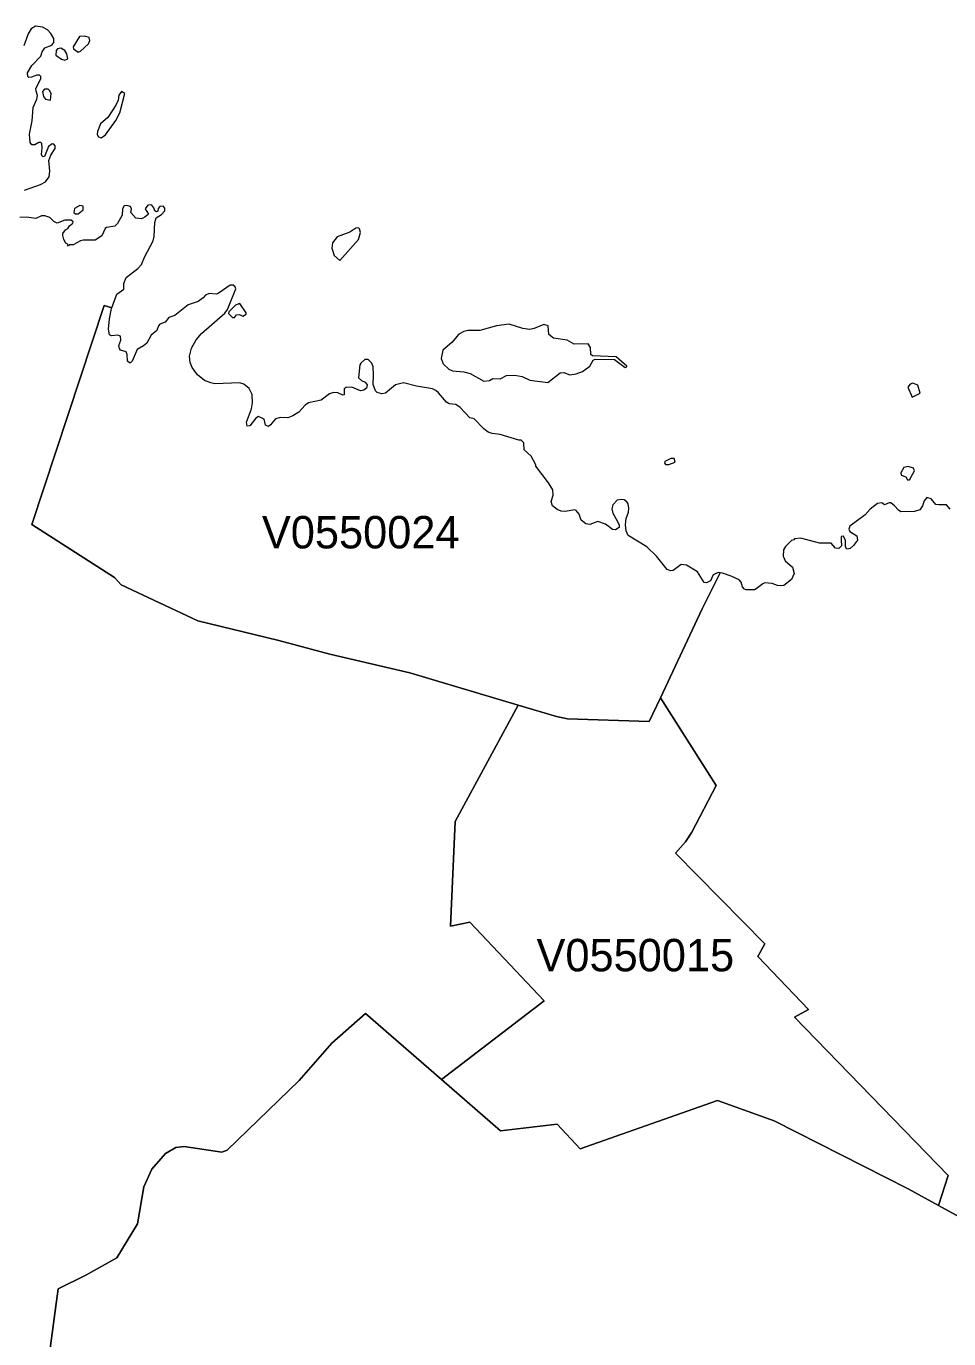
# Model space of a CAD drawing. Extents: x 369010 to 735936, y 6377141 to 6616555.
# Drawn here: x 445399 to 448245, y 6488735 to 6492786 of the extents above; entities that cross this region are included whole.
import ezdxf
from ezdxf.enums import TextEntityAlignment as Align

# ---------------------------------------------------------------- set-up
doc = ezdxf.new("R2010")
doc.units = 0
doc.header["$LTSCALE"] = 40
doc.layers.add('3', color=7, linetype='Continuous', lineweight=13)
doc.layers.add('4', color=7, linetype='Continuous')

msp = doc.modelspace()

# ---------------------------------------------------------------- linework, layer by layer
at = {"layer": '3'}
for points in [[(445393.45, 6492279.97), (445442.77, 6492297.35), (445458.32, 6492305.95), (445469.25, 6492320.68), (445471.56, 6492338.56), (445467.92, 6492371.82), (445474.71, 6492388.54), (445488.11, 6492409.06), (445488.45, 6492416.67), (445484.31, 6492421.8), (445479.18, 6492422.8), (445467.59, 6492414.69), (445455.51, 6492384.4), (445450.71, 6492382.75), (445447.57, 6492384.73), (445446.24, 6492390.03), (445447.9, 6492410.88), (445446.57, 6492423.96), (445443.43, 6492427.27), (445437.97, 6492427.27), (445425.39, 6492419.82), (445416.12, 6492420.15), (445411.32, 6492427.27), (445409.17, 6492452.42), (445417.44, 6492494.13), (445419.76, 6492535.67), (445431.84, 6492560.66), (445433.17, 6492571.92), (445429.03, 6492585.65), (445428.7, 6492593.93), (445443.43, 6492623.72), (445443.43, 6492631), (445440.12, 6492634.81), (445431.18, 6492635.14), (445415.13, 6492629.18), (445406.19, 6492628.19), (445403.38, 6492631), (445402.38, 6492642.59), (445416.12, 6492664.27), (445443.76, 6492693.4), (445447.57, 6492707.13), (445456.17, 6492719.38), (445477.19, 6492727.32), (445483.65, 6492735.27), (445483.65, 6492748.18), (445474.71, 6492763.24), (445464.45, 6492775.32), (445448.56, 6492782.93), (445427.71, 6492785.91), (445413.64, 6492778.13), (445405.03, 6492762.25), (445391.13, 6492725.67)], [(445441.77, 6488475.03), (445489.27, 6488828.22), (445497.55, 6488889.29), (445582.12, 6488931.66), (445678.44, 6488985.11), (445742.16, 6489090.21), (445761.03, 6489203.74), (445786.52, 6489258.69), (445828.72, 6489306.69), (445860.5, 6489326.05), (445885.65, 6489328.53), (446002.67, 6489311.65), (446018.55, 6489317.28), (446240.99, 6489531.94), (446341.29, 6489647.13), (446445.72, 6489739.15), (446679.91, 6489535.25), (446996.35, 6489778.21), (446767.29, 6490021), (446707.71, 6490008.76), (446721.95, 6490331.16), (446916.74, 6490690.96), (446582.59, 6490790.6), (446335.49, 6490848.19), (446177.93, 6490889.73), (445928.02, 6490951.14), (445691.52, 6491062.02), (445671, 6491084.37), (445416.12, 6491248.55), (445639.05, 6491924.13), (445662.39, 6491917.18), (445678.44, 6491959.22), (445699.96, 6491974.45), (445699.96, 6491992.49), (445706.74, 6492010.36), (445742.82, 6492038.17), (445754.08, 6492050.25), (445763.68, 6492073.09), (445789.83, 6492123.9), (445793.3, 6492136.64), (445795.62, 6492179.84), (445800.09, 6492194.57), (445816.47, 6492204.83), (445826.57, 6492216.08), (445826.57, 6492224.69), (445821.27, 6492231.14), (445811.34, 6492229.82), (445806.21, 6492223.03), (445804.23, 6492215.09), (445800.42, 6492213.43), (445795.95, 6492216.08), (445792.48, 6492225.35), (445786.35, 6492233.63), (445782.55, 6492235.28), (445774.11, 6492233.63), (445765.83, 6492222.54), (445775.43, 6492206.15), (445764.84, 6492196.55), (445754.41, 6492191.42), (445737.03, 6492193.74), (445721.14, 6492210.62), (445723.3, 6492222.7), (445720.48, 6492229.49), (445709.56, 6492232.96), (445700.62, 6492232.14), (445696.15, 6492222.21), (445694.5, 6492203.01), (445680.76, 6492177.35), (445671.82, 6492168.75), (445646.17, 6492164.61)], [(445646.17, 6492164.61), (445642.36, 6492161.63), (445631.44, 6492138.63), (445611.25, 6492125.22), (445573.85, 6492125.88), (445566.56, 6492123.9), (445543.89, 6492111.15), (445531.64, 6492111.15), (445529.16, 6492107.35), (445526.18, 6492111.82), (445528.17, 6492112.48), (445520.39, 6492116.28), (445514.76, 6492127.37), (445511.45, 6492140.28), (445512.11, 6492146.57), (445519.89, 6492157.83), (445527.17, 6492161.63), (445531.97, 6492170.07), (445542.9, 6492178.68), (445543.89, 6492182.15), (445537.43, 6492186.95), (445518.24, 6492186.95), (445494.24, 6492178.35), (445483.65, 6492183.15), (445471.56, 6492195.56), (445456.17, 6492200.69), (445446.24, 6492200.36), (445428.04, 6492193.08), (445399.9, 6492196.88), (445378.72, 6492195.23)], [(446424.37, 6491700.87), (446433.31, 6491692.59), (446444.73, 6491687.13), (446450.85, 6491679.19), (446448.86, 6491668.6), (446440.59, 6491662.31), (446430, 6491660.98), (446403.19, 6491671.57), (446385.97, 6491671.24), (446379.19, 6491666.78), (446379.19, 6491647.91), (446376.04, 6491646.91), (446360.32, 6491654.2), (446346.25, 6491655.52), (446334.67, 6491651.38), (446308.19, 6491631.52), (446270.12, 6491623.58), (446259.53, 6491616.46), (446239.34, 6491594.45), (446221.46, 6491583.2), (446205.74, 6491577.07), (446183.07, 6491578.06), (446168, 6491574.26), (446152.61, 6491555.39), (446145.99, 6491550.26), (446136.72, 6491554.4), (446132.59, 6491573.27), (446115.21, 6491581.04), (446106.93, 6491575.91), (446088.4, 6491552.58), (446080.62, 6491551.25), (446078.14, 6491564.33), (446093.53, 6491604.71), (446097.33, 6491623.91), (446095.35, 6491649.4), (446086.74, 6491668.26), (446070.52, 6491681.17), (446057.61, 6491685.64), (445980.82, 6491682), (445968.08, 6491684.98), (445948.88, 6491692.92), (445926.87, 6491709.64), (445910.48, 6491732.65), (445904.69, 6491748.04), (445902.54, 6491767.24), (445908.16, 6491792.72), (445922.89, 6491818.05), (445939.28, 6491837.24), (446011.6, 6491900.63), (446019.88, 6491912.05), (446045.2, 6491975.11), (446043.21, 6491981.89), (446037.09, 6491986.36), (446027.49, 6491986.36), (445991.08, 6491961.04), (445984.63, 6491958.89), (445962.95, 6491961.37), (445951.69, 6491955.91), (445944.41, 6491947.3), (445929.35, 6491936.05), (445898.56, 6491926.45), (445857.35, 6491892.85), (445838.82, 6491887.56), (445827.23, 6491872.5), (445810.68, 6491866.7), (445806.54, 6491860.91), (445802.08, 6491847.17), (445783.7, 6491832.78), (445770.96, 6491808.12), (445760.7, 6491799.18), (445741.17, 6491788.25), (445725.28, 6491751.84), (445720.48, 6491747.04), (445717.5, 6491746.71), (445711.54, 6491752.51), (445710.22, 6491772.37), (445707.24, 6491780.97), (445690.03, 6491786.1), (445686.22, 6491790.9), (445683.91, 6491800.83), (445690.36, 6491817.05), (445689.7, 6491828.97), (445681.42, 6491832.11), (445661.56, 6491830.13), (445655.77, 6491833.44), (445652.96, 6491850.98), (445655.77, 6491882.92), (445661.56, 6491915.03), (445662.39, 6491917.18)], [(445662.39, 6491917.18), (445639.05, 6491924.13), (445416.12, 6491248.55), (445671, 6491084.37), (445691.52, 6491062.02), (445928.02, 6490951.14), (446177.93, 6490889.73), (446335.49, 6490848.19), (446582.59, 6490790.6), (446916.74, 6490690.96), (447034.75, 6490655.71), (447068.68, 6490648.76), (447321.07, 6490640.65), (447355.5, 6490713.64), (447484.42, 6490987.55), (447540.03, 6491098.77), (447533.25, 6491099.76), (447518.19, 6491093.3), (447509.91, 6491074.11), (447497.33, 6491068.48), (447490.71, 6491069.47), (447469.86, 6491102.08), (447435.6, 6491122.76), (447419.38, 6491125.08), (447394.39, 6491106.21), (447387.93, 6491105.22), (447376.18, 6491109.36), (447342.92, 6491150.57), (447313.79, 6491178.87), (447256.19, 6491214.29), (447250.07, 6491228.35), (447247.26, 6491247.55), (447250.07, 6491266.75), (447257.35, 6491285.95), (447258.34, 6491298.86), (447255.53, 6491311.6), (447252.06, 6491318.06), (447243.28, 6491324.02), (447235.67, 6491325.67), (447222.26, 6491322.86), (447208.86, 6491308.96), (447205.55, 6491296.21), (447208.2, 6491283.47), (447222.26, 6491259.8), (447227.73, 6491246.39), (447227.73, 6491238.62), (447216.8, 6491232), (447207.54, 6491232.82), (447185.69, 6491249.21), (447162.68, 6491257.15), (447137.2, 6491248.55), (447125.28, 6491249.87), (447111.21, 6491261.29), (447104.26, 6491279.66), (447095.82, 6491291.41), (447090.36, 6491293.73), (447062.22, 6491288.27), (447049.48, 6491289.59), (447037.07, 6491294.06), (447022.83, 6491306.14), (447018.36, 6491319.22), (447024.49, 6491338.42), (447023.83, 6491355.13), (447010.42, 6491376.81), (446970.7, 6491428.12), (446970.7, 6491431.92), (446956.96, 6491459.4), (446935.28, 6491478.27), (446934.29, 6491500.28), (446925.35, 6491508.39), (446918.9, 6491508.39), (446861.3, 6491526.26), (446835.81, 6491528.74), (446823.57, 6491533.54), (446810.49, 6491543.47), (446781.2, 6491574.26), (446766.96, 6491576.91), (446737.83, 6491609.18), (446724.1, 6491618.12), (446703.24, 6491620.93), (446695.3, 6491625.4), (446670.97, 6491654.86), (446662.7, 6491661.64), (446651.77, 6491666.44), (446602.78, 6491675.38), (446562.57, 6491685.31), (446537.57, 6491679.19), (446506.79, 6491653.04), (446495.37, 6491651.71), (446481.97, 6491655.52), (446476.83, 6491660.32), (446468.73, 6491680.51), (446470.38, 6491709.64), (446469.06, 6491735.13), (446464.59, 6491745.72), (446453.66, 6491756.97), (446443.57, 6491757.31), (446430.66, 6491746.05), (446428.18, 6491741.25), (446424.37, 6491700.87)], [(448249.22, 6491295.22), (448238.46, 6491309.29), (448214.13, 6491308.46), (448205.03, 6491310.28), (448190.63, 6491327.82), (448177.22, 6491331.79), (448169.28, 6491320.87), (448164.48, 6491305.81), (448156.2, 6491293.73), (448139.82, 6491287.94), (448097.62, 6491287.61), (448089.67, 6491292.41), (448078.09, 6491306.14), (448066.5, 6491315.08), (448061.37, 6491315.08), (448046.97, 6491309.29), (448039.03, 6491314.75), (448025.29, 6491312.6), (448002.29, 6491295.22), (447987.56, 6491278.34), (447939.56, 6491242.75), (447937.24, 6491234.15), (447939.56, 6491226.2), (447961.9, 6491212.96), (447963.89, 6491199.56), (447951.14, 6491183.01), (447940.88, 6491174.07), (447930.29, 6491172.08), (447926.15, 6491179.2), (447926.48, 6491198.4), (447920.36, 6491212.47), (447913.58, 6491211.14), (447912.75, 6491199.56), (447914.57, 6491182.34), (447906.29, 6491174.07), (447896.03, 6491174.73), (447882.29, 6491190.29), (447846.05, 6491190.62), (447788.62, 6491205.68), (447769.42, 6491203.69), (447766.77, 6491200.88), (447759.99, 6491199.23), (447741.78, 6491180.69), (447735.49, 6491169.6), (447733.84, 6491150.9), (447740.79, 6491136.17), (447763.3, 6491116.47), (447768.1, 6491096.94), (447759.49, 6491078.08), (447735.99, 6491060.37), (447729.7, 6491058.88), (447716.79, 6491060.04), (447699.91, 6491066.16), (447677.9, 6491067.82), (447671.11, 6491065.17), (447651.25, 6491049.28), (447645.79, 6491046.96), (447620.3, 6491046.3), (447614.84, 6491048.95), (447608.72, 6491055.57), (447604.25, 6491070.3), (447598.79, 6491077.08), (447573.8, 6491088.5), (447547.31, 6491097.61), (447540.03, 6491098.77)], [(447540.03, 6491098.77), (447484.42, 6490987.55), (447355.5, 6490713.64), (447527.95, 6490442.87), (447452.48, 6490298.39), (447433.12, 6490268.93), (447401.67, 6490233.68), (447677.9, 6489954.14), (447656.05, 6489915.08), (447812.29, 6489751.89), (447769.26, 6489728.23), (448243.59, 6489239.49), (448213.96, 6489146.65), (448485.89, 6488997.86)], [(446862.13, 6489376.7), (446679.91, 6489535.25), (446445.72, 6489739.15), (446341.29, 6489647.13), (446240.99, 6489531.94), (446018.55, 6489317.28), (446002.67, 6489311.65), (445885.65, 6489328.53), (445860.5, 6489326.05), (445828.72, 6489306.69), (445786.52, 6489258.69), (445761.03, 6489203.74), (445742.16, 6489090.21), (445678.44, 6488985.11), (445582.12, 6488931.66), (445497.55, 6488889.29), (445489.27, 6488828.22), (445441.77, 6488475.03), (445433.17, 6488413.3)], [(449204.67, 6488728.75), (449205, 6488771.78), (449202.69, 6488788.5), (449191.76, 6488804.55), (449193.09, 6488819.28), (449185.31, 6488830.2), (449164.79, 6488845.92), (449154.86, 6488866.78), (449152.04, 6488883.49), (449144.43, 6488898.22), (449128.71, 6488892.76), (448742.75, 6488821.76), (448485.89, 6488997.86), (448213.96, 6489146.65), (448119.96, 6489198.12), (447706.53, 6489407.81), (447531.1, 6489470.87), (447108.07, 6489321.75), (447036.9, 6489397.55), (446862.13, 6489376.7)]]:
    msp.add_lwpolyline(points, dxfattribs=at)
for points in [[(445578.98, 6492755.13), (445562.76, 6492754.14), (445543.23, 6492722.86), (445544.72, 6492715.74), (445558.78, 6492706.14), (445566.23, 6492709.12), (445590.89, 6492731.79), (445594.7, 6492741.72), (445592.38, 6492751.65)], [(445505.49, 6492718.06), (445494.9, 6492716.07), (445490.76, 6492710.94), (445489.77, 6492696.54), (445507.97, 6492684.13), (445517.9, 6492681.31), (445527.17, 6492685.45), (445524.36, 6492700.51), (445517.9, 6492710.94)], [(445470.9, 6492587.8), (445466.43, 6492591.94), (445454.85, 6492591.94), (445449.06, 6492584.33), (445452.37, 6492568.94), (445458.32, 6492560.99), (445473.05, 6492558.01), (445476.03, 6492577.87)], [(445643.69, 6492450.6), (445674.64, 6492494.79), (445687.22, 6492518.46), (445702.44, 6492578.87), (445692.51, 6492584.66), (445684.24, 6492573.07), (445682.75, 6492558.01), (445674.97, 6492542.79), (445650.64, 6492504.39), (445628.3, 6492484.53), (445618.37, 6492461.53), (445618.03, 6492452.26), (445621.51, 6492445.14), (445629.62, 6492441.33)], [(445564.25, 6492232.63), (445547.36, 6492223.36), (445545.71, 6492210.95), (445550.18, 6492207.48), (445559.12, 6492207.48), (445574.18, 6492219.56), (445574.84, 6492230.15)], [(446423.38, 6492163.29), (446415.27, 6492162.63), (446397.06, 6492150.21), (446358, 6492136.14), (446343.44, 6492117.77), (446342.11, 6492100.56), (446349.07, 6492078.55), (446366.11, 6492062.83), (446424.04, 6492127.37), (446429.67, 6492149.88), (446427.18, 6492160.97)], [(446057.61, 6491930.09), (446044.21, 6491924.63), (446023.35, 6491904.44), (446023.02, 6491899.31), (446034.61, 6491887.23), (446041.39, 6491887.23), (446047.68, 6491894.84), (446056.62, 6491896.16), (446067.21, 6491891.36), (446076.81, 6491897.16), (446077.14, 6491901.29)], [(446888.28, 6491866.7), (446849.22, 6491861.24), (446798.57, 6491847.17), (446761.5, 6491847.17), (446748.76, 6491844.36), (446733.04, 6491835.59), (446711.69, 6491810.1), (446684.38, 6491786.43), (446678.92, 6491760.78), (446685.37, 6491743.57), (446702.58, 6491727.85), (446714.17, 6491722.38), (446748.76, 6491719.57), (446768.29, 6491714.11), (446810.16, 6491690.11), (446828.03, 6491692.59), (446838.46, 6491698.88), (446860.8, 6491697.56), (446880.5, 6491707.99), (446906.15, 6491709.31), (446928.83, 6491704.51), (446952.82, 6491693.92), (447007.94, 6491686.64), (447046.33, 6491716.26), (447057.09, 6491716.92), (447076.29, 6491710.47), (447095.49, 6491713.12), (447114.69, 6491720.4), (447137.69, 6491736.78), (447147.95, 6491754.99), (447153.75, 6491758.3), (447213.99, 6491757.64), (447246.59, 6491732.31), (447252.06, 6491734.3), (447252.06, 6491737.11), (447218.46, 6491765.25), (447145.47, 6491768.39), (447141, 6491773.19), (447139.35, 6491794.05), (447132.89, 6491806.13), (447089.2, 6491804.97), (447068.02, 6491817.38), (447025.15, 6491823.18), (447011.41, 6491834.43), (447008.6, 6491861.57), (446995.69, 6491865.05), (446966.23, 6491852.64), (446952.16, 6491849.99), (446931.14, 6491853.3)], [(448134.69, 6491683.99), (448126.41, 6491681.17), (448118.8, 6491672.4), (448132.21, 6491641.12), (448156.87, 6491653.53), (448150.08, 6491678.53)], [(447400.51, 6491440.86), (447397.86, 6491451.79), (447387.27, 6491452.12), (447368.74, 6491442.52), (447367.74, 6491438.21), (447371.05, 6491433.41), (447381.65, 6491433.08)], [(448119.96, 6491427.46), (448106.22, 6491424.48), (448097.62, 6491407.26), (448098.61, 6491400.81), (448112.35, 6491395.68), (448118.14, 6491386.08), (448124.1, 6491386.41), (448139.49, 6491413.88), (448136.67, 6491421.99)], [(447355.5, 6490713.64), (447321.07, 6490640.65), (447068.68, 6490648.76), (447034.75, 6490655.71), (446916.74, 6490690.96), (446721.95, 6490331.16), (446707.71, 6490008.76), (446767.29, 6490021), (446996.35, 6489778.21), (446679.91, 6489535.25), (446862.13, 6489376.7), (447036.9, 6489397.55), (447108.07, 6489321.75), (447531.1, 6489470.87), (447706.53, 6489407.81), (448119.96, 6489198.12), (448213.96, 6489146.65), (448243.59, 6489239.49), (447769.26, 6489728.23), (447812.29, 6489751.89), (447656.05, 6489915.08), (447677.9, 6489954.14), (447401.67, 6490233.68), (447433.12, 6490268.93), (447452.48, 6490298.39), (447527.95, 6490442.87)]]:
    msp.add_lwpolyline(points, close=True, dxfattribs=at)

# ---------------------------------------------------------------- texts
at = {"layer": '4'}
for s, p in [('V0550024', (446430.72, 6491174.47)), ('V0550015', (447278.03, 6489869.3))]:
    msp.add_text(s, height=100, dxfattribs=at).set_placement(p, align=Align.CENTER)

doc.saveas('drawing.dxf')
